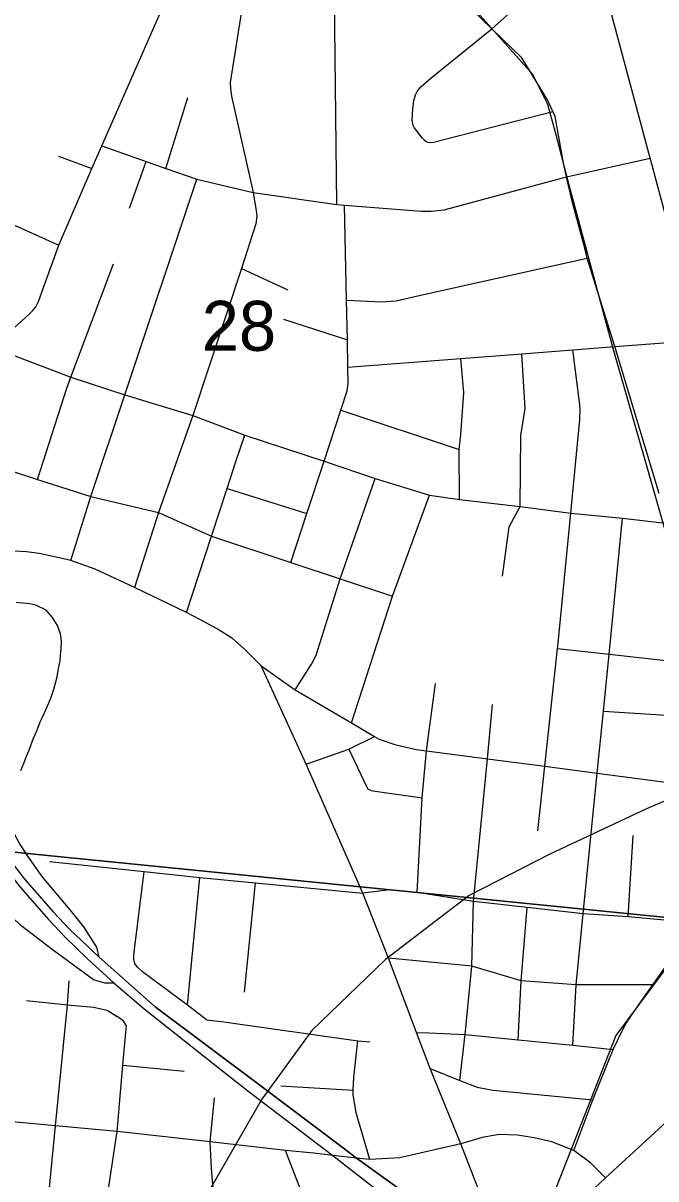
# Model space of a CAD drawing. Extents: x -8.2 to 38.5, y -0.1 to 21.9.
# Drawn here: x 5.137 to 5.667, y 17.89 to 18.858 of the extents above; entities that cross this region are included whole.
import ezdxf

# ---------------------------------------------------------------- set-up
doc = ezdxf.new("R2010")
doc.units = 0
for name, color, linetype in [('GM_X_Adjacent_County_Text', 7, 'Continuous'), ('GM_X_Airport_Location_Class_3', 7, 'Continuous'), ('GM_X_County_Road_Text', 7, 'Continuous'), ('GM_X_Minor_River', 7, 'Continuous'), ('GM_X_State_Location', 7, 'Continuous'), ('GM_X_Township_Subdivision_Text', 7, 'Continuous'), ('GM_X_Township_Text', 7, 'Continuous'), ('GM_X_US_Location', 7, 'Continuous')]:
    doc.layers.add(name, color=color, linetype=linetype)

msp = doc.modelspace()

# ---------------------------------------------------------------- linework, layer by layer
at = {"layer": 'GM_X_Adjacent_County_Text'}
msp.add_lwpolyline([(5.93961, 19.07468), (5.83799, 18.09248), (4.83948, 18.19258), (4.94575, 19.17922)], close=True, dxfattribs=at)
msp.add_lwpolyline([(4.75441, 17.38985), (4.83948, 18.19258), (5.83799, 18.09248), (5.7325, 17.12325), (5.03564, 17.19219)], dxfattribs=at)
at = {"layer": 'GM_X_Airport_Location_Class_3'}
msp.add_line((5.25043, 18.02288), (5.29632, 17.98651), dxfattribs=at)
for points in [[(5.6697, 18.46371), (5.63265, 18.58676), (5.60943, 18.66072), (5.60789, 18.66808), (5.59673, 18.70959), (5.5923, 18.72893), (5.58935, 18.74182), (5.58259, 18.77934), (5.58069, 18.78357), (5.57634, 18.79329), (5.55466, 18.8284), (5.52968, 18.85273), (5.48612, 18.89515)], [(5.20069, 18.07549), (5.19877, 18.08399), (5.188, 18.10083), (5.17789, 18.11335), (5.15294, 18.14309), (5.14056, 18.1608), (5.13343, 18.17193), (5.12624, 18.18514), (5.11815, 18.20181), (5.11289, 18.21405), (5.10812, 18.22595), (5.10389, 18.23547), (5.09839, 18.25121), (5.09696, 18.25603), (5.07444, 18.32695), (5.0517, 18.38554), (5.05002, 18.3895), (5.03134, 18.44025), (5.02967, 18.44478), (5.0256, 18.45583), (5.02053, 18.46952), (5.01729, 18.47942), (5.0148, 18.49062), (5.01022, 18.5218)], [(4.96268, 18.31222), (4.99393, 18.28942), (5.01981, 18.26837), (5.04826, 18.23998), (5.07683, 18.20608), (5.12396, 18.14776), (5.13452, 18.13414), (5.15842, 18.10716), (5.17224, 18.09225), (5.19045, 18.0747), (5.19454, 18.07088), (5.21332, 18.05385)], [(5.21332, 18.05385), (5.20565, 18.05382), (5.19597, 18.05666), (5.16147, 18.08193), (5.13531, 18.10198), (5.12791, 18.109), (5.12377, 18.11354)], [(5.59883, 17.67204), (5.59746, 17.67656), (5.58298, 17.72409), (5.58161, 17.72708), (5.56894, 17.75479), (5.55447, 17.78002), (5.54008, 17.79971), (5.53161, 17.81077), (5.52289, 17.82015), (5.50709, 17.83638), (5.49339, 17.84965), (5.48154, 17.86018), (5.46608, 17.87148), (5.41629, 17.90733), (5.40533, 17.91556), (5.33437, 17.96919), (5.24763, 18.034), (5.20069, 18.07549)], [(5.21332, 18.05385), (5.2382, 18.03257), (5.25043, 18.02288)], [(5.29632, 17.98651), (5.32538, 17.96348), (5.39662, 17.90939), (5.45588, 17.86325), (5.47134, 17.85196), (5.48132, 17.8434), (5.488, 17.83765)]]:
    msp.add_lwpolyline(points, dxfattribs=at)
at = {"layer": 'GM_X_Minor_River'}
msp.add_lwpolyline([(5.13513, 18.2318), (5.13797, 18.23857), (5.14002, 18.24385), (5.14205, 18.24874), (5.14371, 18.25365), (5.14575, 18.25892), (5.14858, 18.26494), (5.15144, 18.27247), (5.15347, 18.27699), (5.15709, 18.2845), (5.16035, 18.29241), (5.16283, 18.29995), (5.16536, 18.30902), (5.16626, 18.31395), (5.16714, 18.31849), (5.16803, 18.32342), (5.16854, 18.32798), (5.16906, 18.33329), (5.16925, 18.34014), (5.16827, 18.34626), (5.1658, 18.35319), (5.16179, 18.35977), (5.15626, 18.36602), (5.14762, 18.37007), (5.14271, 18.37135), (5.13133, 18.37243)], dxfattribs=at)
at = {"layer": 'GM_X_State_Location'}
msp.add_line((5.25043, 18.02288), (5.29632, 17.98651), dxfattribs=at)
for points in [[(4.96268, 18.31222), (4.99393, 18.28942), (5.01981, 18.26837), (5.04826, 18.23998), (5.07683, 18.20608), (5.12396, 18.14776), (5.13452, 18.13414), (5.15842, 18.10716), (5.17224, 18.09225), (5.19045, 18.0747), (5.19454, 18.07088), (5.21332, 18.05385)], [(5.1214, 18.16247), (5.13845, 18.1405), (5.16236, 18.11353), (5.17618, 18.09861), (5.20069, 18.07549)], [(5.20069, 18.07549), (5.24763, 18.034), (5.33437, 17.96919), (5.40533, 17.91556), (5.41629, 17.90733), (5.46608, 17.87148), (5.48154, 17.86018), (5.49339, 17.84965), (5.50709, 17.83638), (5.52289, 17.82015), (5.53161, 17.81077), (5.54008, 17.79971), (5.55447, 17.78002), (5.56894, 17.75479), (5.58161, 17.72708), (5.58298, 17.72409), (5.59746, 17.67656), (5.59883, 17.67204)], [(5.21332, 18.05385), (5.2382, 18.03257), (5.25043, 18.02288)], [(5.29632, 17.98651), (5.32538, 17.96348), (5.39662, 17.90939), (5.45588, 17.86325), (5.47134, 17.85196), (5.48132, 17.8434), (5.488, 17.83765)]]:
    msp.add_lwpolyline(points, dxfattribs=at)
at = {"layer": 'GM_X_Township_Subdivision_Text'}
for p, q in [((5.25668, 18.73589), (5.27498, 18.7951)), ((5.16666, 18.74613), (5.19476, 18.73584)), ((5.5923, 18.72893), (5.66233, 18.74455)), ((5.22632, 18.70262), (5.24007, 18.74173)), ((5.32009, 18.65219), (5.35885, 18.63433)), ((5.35513, 18.60974), (5.4087, 18.59229)), ((5.40318, 18.53342), (5.50234, 18.50042)), ((5.30788, 18.46789), (5.37485, 18.44704)), ((5.62311, 18.2814), (5.704, 18.27618)), ((5.64387, 18.10928), (5.64813, 18.17737)), ((5.27464, 18.03538), (5.28516, 18.14208)), ((5.32245, 18.04612), (5.33185, 18.13764)), ((5.22055, 17.98523), (5.27201, 17.98014)), ((5.35282, 17.96774), (5.41357, 17.96419)), ((5.29371, 17.92079), (5.29732, 17.95761))]:
    msp.add_line(p, q, dxfattribs=at)
for points in [[(5.39983, 18.70553), (5.39771, 18.90366), (5.39724, 18.96085), (5.41019, 19.0113), (5.4138, 19.06271), (5.41735, 19.11339)], [(5.70338, 18.59204), (5.68803, 18.64905), (5.67743, 18.68846), (5.66422, 18.73755), (5.66233, 18.74455), (5.62818, 18.87142), (5.62675, 18.87487), (5.62511, 18.87714), (5.6212, 18.87997), (5.61669, 18.88162), (5.60648, 18.88304), (5.59396, 18.88377), (5.58965, 18.88366), (5.58108, 18.88183), (5.57089, 18.87958), (5.56302, 18.87704), (5.55397, 18.87266), (5.54954, 18.87021), (5.52968, 18.85273)], [(5.47135, 18.76147), (5.46463, 18.77001), (5.4639, 18.77173), (5.46307, 18.77638), (5.4634, 18.78605), (5.46423, 18.79244), (5.46586, 18.79736), (5.4671, 18.80034), (5.47025, 18.80405), (5.47882, 18.81179), (5.52968, 18.85273)], [(5.47135, 18.76147), (5.47298, 18.75965), (5.47468, 18.75834), (5.47615, 18.75778), (5.47774, 18.75756), (5.48074, 18.75779), (5.58069, 18.78357)], [(5.20294, 18.75481), (5.24007, 18.74173), (5.25668, 18.73589), (5.2826, 18.72675), (5.32979, 18.71581)], [(5.01775, 18.74035), (5.03233, 18.7342), (5.09921, 18.70208), (5.16711, 18.67169)], [(5.17719, 18.40758), (5.19385, 18.46108), (5.22232, 18.5463), (5.2826, 18.72675)], [(5.36139, 18.40601), (5.37485, 18.44704), (5.38916, 18.4907), (5.40318, 18.53342), (5.40853, 18.54974), (5.40945, 18.55579), (5.40917, 18.56943), (5.4087, 18.59229), (5.408, 18.62565), (5.40635, 18.70504)], [(5.14912, 18.47551), (5.17371, 18.55199), (5.17693, 18.56101), (5.21287, 18.65589)], [(5.408, 18.62565), (5.43735, 18.62412), (5.4495, 18.62498), (5.47239, 18.63039), (5.60943, 18.66072)], [(5.40917, 18.56943), (5.50382, 18.57678), (5.55479, 18.58074), (5.59743, 18.58405), (5.63265, 18.58676), (5.70338, 18.59204), (5.73644, 18.59451), (5.78841, 18.59839), (5.83983, 18.60222), (5.84218, 18.60232), (5.86085, 18.60307), (5.89037, 18.60425), (5.9812, 18.60788), (6.06298, 18.61116)], [(5.53861, 18.39446), (5.54404, 18.43575), (5.55352, 18.45276), (5.55408, 18.51213), (5.55752, 18.53482), (5.55479, 18.58074)], [(5.56806, 18.18131), (5.57394, 18.23532), (5.58468, 18.33385), (5.58486, 18.33547), (5.59578, 18.4472), (5.59975, 18.48789), (5.60341, 18.52528), (5.60376, 18.53371), (5.60338, 18.53782), (5.59743, 18.58405)], [(5.50265, 18.45866), (5.50234, 18.50042), (5.50358, 18.51288), (5.50607, 18.54814), (5.50382, 18.57678)], [(5.27386, 18.3641), (5.29483, 18.42809), (5.30788, 18.46789), (5.315, 18.48962), (5.32274, 18.51248)], [(5.05681, 18.50527), (5.1038, 18.49012), (5.14912, 18.47551), (5.19385, 18.46108), (5.25039, 18.44767), (5.29483, 18.42809), (5.36139, 18.40601), (5.40264, 18.39232), (5.44654, 18.37775)], [(5.36508, 18.29943), (5.37864, 18.32074), (5.38264, 18.32822), (5.40264, 18.39232), (5.43187, 18.47635)], [(5.41209, 18.27171), (5.44654, 18.37775), (5.47758, 18.46235)], [(5.59759, 18.0019), (5.60023, 18.05222), (5.60612, 18.11187), (5.61776, 18.22954), (5.62311, 18.2814), (5.62804, 18.32908), (5.63905, 18.44318)], [(5.58468, 18.33385), (5.62804, 18.32908), (5.70045, 18.32113)], [(5.46706, 18.12975), (5.47122, 18.20901), (5.47497, 18.24837), (5.48243, 18.30454)], [(5.50286, 17.97234), (5.50736, 18.01063), (5.51295, 18.06786), (5.5144, 18.12217), (5.52594, 18.24165), (5.53033, 18.28717)], [(5.37415, 18.23716), (5.40984, 18.24969), (5.43148, 18.26028)], [(5.40984, 18.24969), (5.42455, 18.21836), (5.42563, 18.21685), (5.42641, 18.21605), (5.42738, 18.21548), (5.42868, 18.2151), (5.43206, 18.21442), (5.47122, 18.20901)], [(5.15906, 18.15572), (5.23847, 18.14717), (5.28516, 18.14208), (5.33185, 18.13764), (5.42162, 18.12907)], [(5.29075, 18.02305), (5.27464, 18.03538), (5.23715, 18.06333), (5.23288, 18.06727), (5.23074, 18.07023), (5.22992, 18.07385), (5.22992, 18.07747), (5.23847, 18.14717)], [(5.55173, 18.00638), (5.55426, 18.0557), (5.55937, 18.11712)], [(5.66441, 18.0524), (5.60023, 18.05222), (5.55426, 18.0557), (5.51295, 18.06786), (5.44303, 18.07477)], [(5.14064, 17.68332), (5.14802, 17.77192), (5.15156, 17.80491), (5.1642, 17.93444), (5.17435, 18.03571), (5.17566, 18.05576)], [(5.13982, 18.03932), (5.17435, 18.03571), (5.19605, 18.03357), (5.2074, 18.03127), (5.21594, 18.02585)], [(5.18825, 17.67325), (5.19873, 17.76532), (5.20177, 17.81669), (5.20684, 17.87041), (5.21582, 17.9295), (5.22055, 17.98523), (5.22318, 18.01236), (5.22367, 18.01812), (5.22104, 18.0219), (5.21594, 18.02585)], [(5.29075, 18.02305), (5.30521, 18.02124), (5.41731, 18.00554), (5.42747, 18.00452)], [(5.46658, 18.01236), (5.47689, 18.01221), (5.50736, 18.01063), (5.55173, 18.00638), (5.59759, 18.0019), (5.63121, 17.99815)], [(5.42757, 17.90616), (5.41603, 17.94514), (5.41343, 17.96051), (5.41357, 17.96419), (5.41398, 17.97517), (5.41731, 18.00554)], [(5.47794, 17.98218), (5.50286, 17.97234), (5.51735, 17.9668), (5.53052, 17.96426), (5.61428, 17.95606)], [(5.42368, 17.74018), (5.41956, 17.75089), (5.35688, 17.91372)]]:
    msp.add_lwpolyline(points, dxfattribs=at)
at = {"layer": 'GM_X_Township_Text'}
for p, q in [((5.44303, 18.07477), (5.42162, 18.12907)), ((5.46658, 18.01236), (5.44303, 18.07477)), ((5.47794, 17.98218), (5.46658, 18.01236)), ((5.50378, 17.91914), (5.47794, 17.98218))]:
    msp.add_line(p, q, dxfattribs=at)
for points in [[(5.15039, 18.62521), (5.16711, 18.67169), (5.19476, 18.73584), (5.20294, 18.75481), (5.30892, 18.99546)], [(5.32503, 18.89929), (5.31056, 18.80772), (5.31072, 18.80261), (5.31171, 18.79637), (5.32979, 18.71581), (5.33226, 18.70036), (5.33292, 18.69576), (5.33193, 18.68951), (5.32009, 18.65219), (5.27916, 18.52905), (5.25039, 18.44767), (5.23049, 18.38503)], [(5.32979, 18.71581), (5.39983, 18.70553), (5.40635, 18.70504), (5.47081, 18.70019), (5.47877, 18.7), (5.48981, 18.70124), (5.5923, 18.72893)], [(5.01022, 18.5218), (5.01577, 18.5258), (5.03496, 18.5395), (5.09429, 18.57771), (5.10844, 18.58693), (5.11721, 18.59164), (5.14182, 18.61366), (5.14496, 18.61664), (5.14781, 18.62004), (5.15011, 18.62443), (5.15039, 18.62521)], [(5.10844, 18.58693), (5.13465, 18.57717), (5.17693, 18.56101), (5.22232, 18.5463), (5.27916, 18.52905), (5.32274, 18.51248), (5.38916, 18.4907), (5.43187, 18.47635), (5.47758, 18.46235), (5.50265, 18.45866), (5.55352, 18.45276), (5.59578, 18.4472), (5.63905, 18.44318), (5.67517, 18.43875), (5.72118, 18.43437), (5.77244, 18.4248), (5.82139, 18.42013), (5.8678, 18.4157), (5.86866, 18.41573), (5.91336, 18.41727), (5.98824, 18.41986), (6.06604, 18.42255)], [(5.33643, 18.31941), (5.32217, 18.33366), (5.31252, 18.34222), (5.29892, 18.35077), (5.28576, 18.35779), (5.27386, 18.3641), (5.23049, 18.38503), (5.19744, 18.40022), (5.17719, 18.40758), (5.16482, 18.41032), (5.15049, 18.41351), (5.14005, 18.41494), (5.13007, 18.41549), (5.12097, 18.41516), (5.11275, 18.41472), (5.10222, 18.41209), (5.09487, 18.40957), (5.08456, 18.40507), (5.05002, 18.3895)], [(5.33643, 18.31941), (5.36508, 18.29943), (5.41209, 18.27171), (5.43148, 18.26028), (5.43538, 18.25798), (5.44854, 18.25343), (5.46628, 18.24951), (5.47497, 18.24837), (5.52594, 18.24165), (5.57394, 18.23532), (5.61776, 18.22954), (5.70267, 18.21835), (5.82759, 18.20501)], [(5.42162, 18.12907), (5.37415, 18.23716), (5.33643, 18.31941)], [(5.60612, 18.11187), (5.55937, 18.11712), (5.5144, 18.12217), (5.46706, 18.12975), (5.44455, 18.13183), (5.42162, 18.12907)], [(5.69796, 18.10419), (5.68924, 18.10518), (5.64387, 18.10928), (5.60612, 18.11187)], [(5.59834, 17.91377), (5.61428, 17.95606), (5.63121, 17.99815), (5.63976, 18.01546), (5.64277, 18.02104), (5.65504, 18.03908), (5.66441, 18.0524), (5.67894, 18.07261), (5.68957, 18.08512), (5.69927, 18.09317)], [(5.76852, 18.06919), (5.76707, 18.06645), (5.7572, 18.04196), (5.7434, 18.01334), (5.73583, 18.00184), (5.71691, 17.97934), (5.71183, 17.9734), (5.69292, 17.95334), (5.62496, 17.89079)], [(5.35688, 17.91372), (5.29371, 17.92079), (5.21582, 17.9295), (5.1642, 17.93444), (5.1157, 17.93887)], [(5.72445, 17.60743), (5.68402, 17.62944), (5.6727, 17.6356), (5.66459, 17.64002), (5.62653, 17.66074), (5.60348, 17.67329), (5.59746, 17.67656), (5.57279, 17.68998), (5.53225, 17.71205), (5.44212, 17.7383), (5.41956, 17.75089), (5.35227, 17.78843), (5.3263, 17.81159), (5.30142, 17.86069), (5.2966, 17.87943), (5.295, 17.8987), (5.29371, 17.92079)], [(5.51313, 17.92198), (5.50378, 17.91914), (5.45256, 17.90747), (5.42757, 17.90616), (5.41629, 17.90733), (5.39662, 17.90939), (5.38055, 17.91142), (5.35688, 17.91372)], [(5.59834, 17.91377), (5.57977, 17.92097), (5.56505, 17.92428), (5.55116, 17.92651), (5.5359, 17.92691), (5.52156, 17.92453), (5.51313, 17.92198)], [(5.55262, 17.8207), (5.54381, 17.83175), (5.53679, 17.84132), (5.53052, 17.85117), (5.52678, 17.85954), (5.50378, 17.91914)], [(5.62496, 17.89079), (5.61251, 17.90306), (5.59834, 17.91377)], [(5.62496, 17.89079), (5.60589, 17.87303), (5.56939, 17.83851), (5.55262, 17.8207), (5.54478, 17.80876), (5.54243, 17.80424)]]:
    msp.add_lwpolyline(points, dxfattribs=at)
at = {"layer": 'GM_X_US_Location'}
for points in [[(5.51755, 18.86635), (5.56383, 18.8147), (5.57629, 18.78976), (5.58341, 18.76305), (5.59409, 18.72209), (5.63056, 18.58726), (5.69733, 18.35339), (5.70445, 18.30351), (5.70445, 18.25364), (5.70055, 18.21721)], [(5.70055, 18.21721), (5.65914, 18.1997), (5.57835, 18.16166), (5.51066, 18.12721), (5.44065, 18.07343), (5.37877, 18.01424), (5.33689, 17.9566), (5.28911, 17.87309), (5.26824, 17.81194), (5.21734, 17.65871), (5.14005, 17.41698)], [(5.69953, 18.09843), (5.63364, 18.00993), (5.56924, 17.84642)]]:
    msp.add_lwpolyline(points, dxfattribs=at)

# ---------------------------------------------------------------- texts
at = {"layer": 'GM_X_County_Road_Text'}
msp.add_text('28', height=0.041856, rotation=0.00001, dxfattribs=at).set_placement((5.28672, 18.58314))

doc.saveas('drawing.dxf')
